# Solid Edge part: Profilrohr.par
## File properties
Username: ahadarics
Dokumentum tartalom típus: 0
Author: ahadarics
Last saved by: ahadarics
Revision: 79
Sűrűség: 0,000 kg/m^3
Pontosság: 0,990
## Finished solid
Body 1: solid body, 115 faces, 338 edges, 224 vertices.
  Faces by surface: cylinder 59, plane 56
  Edges by curve: line 220, circle 118
Bounding box of the edges (mm): 113.500 x 113.500 x 48.000, from (-56.75, -56.75, -31.5) to (56.75, 56.75, 16.5).
Cylindrical faces by radius (mm): R0.15 x24, R0.25 x24, R1 x4, R12.25 x4, R35 x2, R50 x1
Planar faces by outward normal: +x 13, +y 14, +z 1, -x 13, -y 14, -z 1
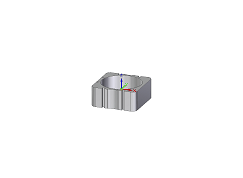
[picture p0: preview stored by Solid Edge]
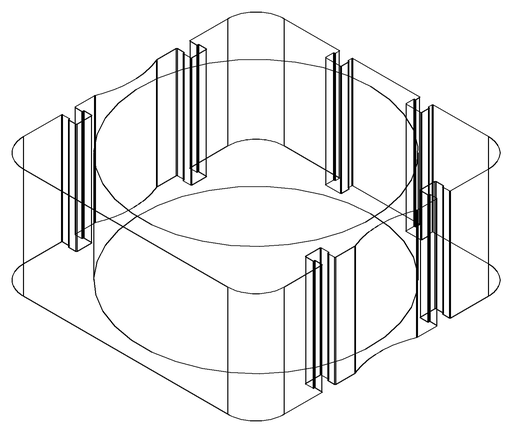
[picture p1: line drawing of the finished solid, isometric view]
